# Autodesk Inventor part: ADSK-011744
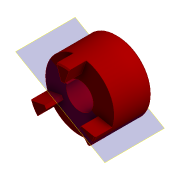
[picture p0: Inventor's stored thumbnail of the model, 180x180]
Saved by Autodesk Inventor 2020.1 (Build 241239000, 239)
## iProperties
Created: 2000-03
Part Number: ADSK-011744
Material: Pearson HRS
Description: COUPLING,JAW,L100,1.00BORE, .25 KEY
Document SubType Name: Modeling
Designer: cmcgourin
Density: 7.83 g/cm^3
Appearance: Red(Flat)
Mass: 790.898 g
Surface Area: 173.543 cm^2
Volume: 101.009 cm^3
Control State: 0
Master: False
Checked Out: False
Shininess: 0.0
Length Units: 11269
Angle Units: 11279
Time Units: 11290
Mass Units: 11283
Length Display Precision: 3
Angle Display Precision: 2
Compacted: True
Cutlength: 23.25
Material Desc: Material Description goes here
Material_Number: Pearson
Dimensions: 64,5x51x64,5 mm
Mass: 0,791 kg
VLT_Material: Pearson HRS
Density: 0.0
Volumn: 0.0
Area: 0.0
PropertySet Name: Model Information
Author: cmcgourin
Revision Number: -
Title: COUPLING,JAW,L100,1.00BORE, .25 KEY
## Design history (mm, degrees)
workplane "Arbeitsebene1"
node "Circular Pattern1" dims "d24" = 30, "d26" = 120 deg
node "Solide1"
  node "Extrusion1" dims "d1" = 35, "d2" = 0
  node "Extrusion2" dims "d22" = 16, "d23" = 0
  node "Extrusion3" dims "d27" = 15.875, "d28" = 0
  node "Chamfer1" dims "d29" = 1, "d30" = 1, "d31" = 45 deg
sketch "Sketch1"
  geometry: C1 r 32.25 at (0, 0); C2 r 12.5 at (0, 0); 2 further points
  constraints: 2 centre point, 2 coincident
  dimensions: "d0" = 64.5 diameter of C1; "d32" = 25 diameter of C2
sketch "Sketch3"
  geometry: L1 (0, 0)-(0, 32.25); L2 (-1.6, 19.936)-(-6, 31.687); L3 (1.6, 19.936)-(6, 31.687); A1 r 32.25 centre (0, 0) between (0, 32.25) and (-6, 31.687) reference; A2 r 20 centre (0, 0) between (-1.6, 19.936) and (1.6, 19.936)
  constraints: 6 end point, 5 point on circle, 1 centre point, 1 coincident, 1 vertical
  dimensions: "d17" = 40 diameter of A2; "d18" = 6 horizontal distance of A1.centre L2.end (= d19); "d19" = 6 horizontal distance of A1.centre L3.end; "d20" = 1.6 distance from line of L1 L2.start (= d21); "d21" = 1.6 distance from line of L1 L3.start
sketch "Sketch4"
  geometry: L1 (0, 0)-(-12.5, 0); L2 (0, 0)-(-10.825, 6.25); L3 (-12.009, 3.469)-(-14.49, 4.902); L4 (-14.49, 4.902)-(-11.49, 10.098); L5 (-11.49, 10.098)-(-9.009, 8.665); A1 r 12.5 centre (0, 0) between (-12.5, 0) and (-10.825, 6.25) reference; 1 further point
  constraints: 10 end point, 4 point on circle, 2 perpendicular, 1 horizontal, 1 midpoint, 1 point on line
  dimensions: "d33" = 30 deg angle of L2 L1; "d34" = 6 distance of L3.end L4.end; "d35" = 2.5 distance from line of L2.end L4
node "Corps solides"
node "Corps surfaciques"
